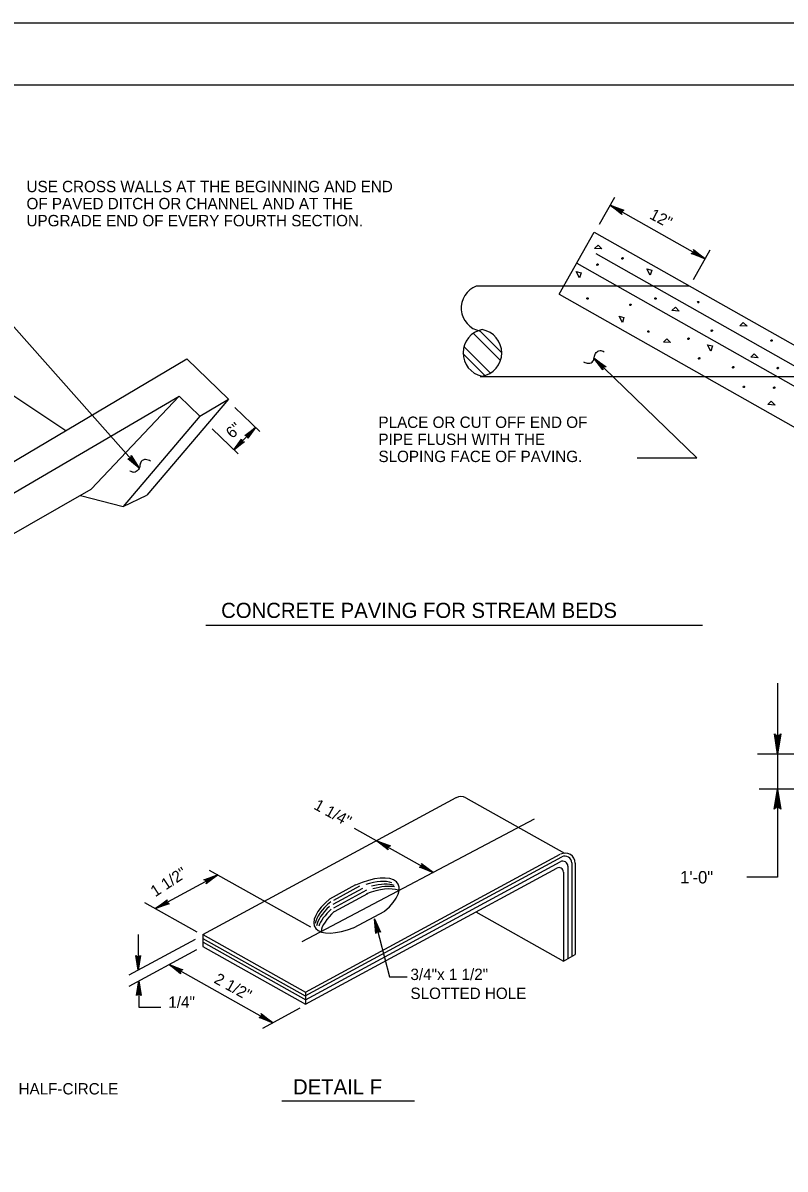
# Model space of a CAD drawing. Extents: x 5 to 910, y -47 to 547.
# Drawn here: x 180.3 to 364.1, y 270.9 to 547.5 of the extents above; entities that cross this region are included whole.
import ezdxf

# ---------------------------------------------------------------- set-up
doc = ezdxf.new("R2010")
doc.units = 0
for name, color, linetype in [('1', 7, 'Continuous'), ('2', 7, 'Continuous'), ('3', 7, 'Continuous'), ('PLT-BNDY', 7, 'Continuous')]:
    doc.layers.add(name, color=color, linetype=linetype)

msp = doc.modelspace()

# ---------------------------------------------------------------- linework, layer by layer
at = {"layer": '1'}
msp.add_line((289.63, 484), (340.95, 484), dxfattribs=at)
msp.add_lwpolyline([(830.72, -31.53), (830.72, 532.47), (44.72, 532.47), (44.72, -31.53), (830.72, -31.53), (830.72, -5.17), (630.72, -5.17), (630.72, 59.51), (830.72, 59.51), (830.72, 88.47), (630.72, 88.47), (630.72, -31.53), (709.52, -31.53), (709.52, -5.17), (709.52, -31.53), (786.52, -31.53), (786.52, -5.17), (786.52, -17.48), (830.72, -17.48)], dxfattribs=at)
for points in [[(318.98, 493.88), (319.9, 492.94), (318.16, 493.08)], [(314.89, 487.18), (314.54, 485.94), (313.74, 487.5)], [(331.91, 487.82), (331.57, 486.58), (330.77, 488.14)], [(337.63, 478.9), (338.54, 477.96), (336.81, 478.1)], [(325.23, 476.43), (324.89, 475.19), (324.09, 476.75)], [(354.01, 475.21), (354.93, 474.28), (353.19, 474.41)], [(335.57, 471.28), (336.49, 470.34), (334.75, 470.48)], [(346.55, 469.52), (346.21, 468.28), (345.41, 469.84)], [(356.66, 467.62), (357.58, 466.68), (355.84, 466.82)], [(360.76, 456.2), (361.67, 455.26), (359.94, 455.4)]]:
    msp.add_lwpolyline(points, close=True, dxfattribs=at)
for centre in [(324.86, 490.66), (318.82, 489.15), (316.46, 480.98), (326.81, 479.47), (332.82, 480.98), (343.16, 480.11), (331.11, 473.02), (346.39, 473.22), (340.78, 471.28), (360.8, 470.84), (343.37, 466.54), (351.56, 464.39), (362.31, 464.19), (354.15, 459.66), (361.47, 459.45)]:
    msp.add_ellipse(centre, major_axis=(-0.048, -0.184), ratio=0.9, dxfattribs=at)
at = {"layer": '2'}
for p, q in [((319.3, 498.92), (323.03, 505.46)), ((321.91, 503.49), (344.79, 490.57)), ((309.6, 482.01), (318.05, 496.95)), ((318.05, 496.95), (379.59, 462.15)), ((342, 485.6), (346.03, 492.74)), ((318.43, 491.8), (378.44, 457.87)), ((313.84, 489.49), (377.32, 453.59)), ((309.6, 482.01), (375.08, 444.99)), ((178.09, 474.18), (208.3, 440.06)), ((290.52, 473.13), (295.76, 467.89)), ((288.92, 472.56), (295.46, 466.04)), ((286.4, 467.69), (291.85, 462.26)), ((286.63, 469.36), (293.04, 462.95)), ((159.77, 430.8), (219.81, 466.4)), ((219.81, 466.4), (229.83, 456.67)), ((318, 466.57), (342.77, 442.57)), ((290.57, 462.15), (379.59, 462.15)), ((174.96, 459.62), (190.66, 449.12)), ((164.58, 426.13), (217.93, 457.43)), ((196.77, 434.94), (217.95, 457.45)), ((229.83, 456.67), (210.15, 433.52)), ((217.95, 457.45), (222.96, 452.6)), ((222.96, 452.6), (229.83, 456.67)), ((222.96, 452.6), (229.83, 456.67)), ((231.38, 454.68), (237.38, 448.87)), ((222.96, 452.6), (204.43, 430.8)), ((225.94, 449.56), (232.18, 443.49)), ((231.18, 444.48), (236.39, 449.83)), ((328.42, 442.57), (342.77, 442.57)), ((142.93, 404.33), (196.77, 434.94)), ((194.16, 433.45), (204.43, 430.8)), ((204.43, 430.8), (210.15, 433.52)), ((344.2, 402.04), (224.36, 402.04)), ((362.28, 388.19), (362.28, 371.06)), ((426.73, 371.06), (357.43, 371.06)), ((362.28, 371.06), (362.28, 362.6)), ((380.12, 362.6), (357.86, 362.6)), ((362.28, 362.6), (362.28, 341.37)), ((223.68, 327.49), (284.74, 360.55)), ((287.1, 360.53), (310.91, 347.16)), ((303.57, 355.33), (247.56, 325.73)), ((260.15, 353.21), (279.2, 342.5)), ((248.34, 312.73), (310.23, 346.23)), ((248.45, 313.6), (309.88, 346.87)), ((225.23, 343.05), (249.62, 329.34)), ((248.43, 311.79), (309.86, 345.06)), ((248.45, 310.74), (309.01, 343.55)), ((311.69, 343.98), (311.69, 321.68)), ((312.65, 344.79), (312.65, 322.23)), ((313.5, 344.72), (313.5, 322.68)), ((212.24, 333.76), (227.29, 341.9)), ((310.64, 342.57), (310.64, 321.11)), ((362.28, 341.37), (354.84, 341.37)), ((254.33, 336.16), (260.58, 339.55)), ((255.14, 334.83), (262.27, 338.7)), ((255.25, 333.94), (263.23, 338.29)), ((255.27, 335.84), (261.54, 339.25)), ((255.39, 333.05), (263.44, 337.42)), ((209.61, 335.22), (222.21, 328.15)), ((260.03, 329.14), (267.54, 333.19)), ((289.48, 332.96), (310.64, 321.11)), ((265.06, 331.33), (268.68, 317.33)), ((205.9, 317.77), (221.87, 326.41)), ((208.05, 327.49), (208.05, 318.93)), ((223.65, 326.57), (248.34, 312.73)), ((223.68, 327.49), (248.45, 313.6)), ((223.68, 327.49), (223.68, 324.63)), ((205.92, 315.04), (222.19, 323.87)), ((223.68, 324.63), (248.45, 310.74)), ((223.75, 325.64), (248.52, 311.75)), ((310.64, 321.11), (313.5, 322.68)), ((215.56, 320.26), (240.54, 306.23)), ((208.23, 316.32), (208.23, 309.96)), ((268.68, 317.33), (272.93, 317.33)), ((248.45, 313.6), (248.45, 310.74)), ((208.23, 309.96), (213.56, 309.96)), ((238.14, 304.95), (247.13, 309.83)), ((274.72, 287.31), (242.75, 287.31))]:
    msp.add_line(p, q, dxfattribs=at)
for centre, radius, start, end in [((291.66, 478.69), 5.68, 111.014, 258.5133), ((292.15, 467.86), 5.73, 101.3755, 257.9127), ((290.08, 467.87), 5.68, 278.8417, 80.4465), ((285.9, 358.39), 2.44, 60.7347, 118.4286), ((311.05, 344.72), 2.44, 0, 118.4349), ((311, 344.78), 1.65, 0, 118.4241), ((309.54, 342.57), 1.1, 0, 118.4375), ((310.46, 343.98), 1.24, 0, 118.4388)]:
    msp.add_arc(centre, radius, start, end, dxfattribs=at)
for centre, start_param, end_param in [((260.85, 334.36), 2.061561, 4.528802), ((260.76, 333.54), 3.509765, 4.274889), ((262.36, 331.73), 3.509765, 4.413542), ((261.34, 332.88), 3.509765, 4.189593), ((262.14, 332.37), 3.627721, 4.236382), ((260.63, 334.64), 5.155673, 7.585653), ((260.95, 334.04), 5.174005, 5.990096), ((261.29, 333.47), 5.255034, 5.990096), ((261.68, 332.74), 5.250975, 5.872331), ((262.34, 332.12), 5.242115, 5.990096)]:
    msp.add_ellipse(centre, major_axis=(-9.95, -5.32), ratio=0.421892, start_param=start_param, end_param=end_param, dxfattribs=at)
at = {"layer": '3'}
for points in [[(324.61, 501.5), (324.61, 501.75), (321.91, 503.49), (324.61, 501.5), (324.68, 501.27), (321.91, 503.49), (324.77, 502.05), (325, 502.21), (321.91, 503.49), (325.23, 502.26), (325, 502.21)], [(342.09, 492.56), (342.09, 492.3), (344.79, 490.57), (342.09, 492.56), (342.02, 492.78), (344.79, 490.57), (341.93, 492.01), (341.7, 491.85), (344.79, 490.57), (341.47, 491.8), (341.7, 491.85)], [(320.1, 463.96), (320.17, 464.21), (318, 466.57), (320.1, 463.96), (320.13, 463.73), (318, 466.57), (320.4, 464.46), (320.65, 464.55), (318, 466.57), (320.9, 464.53), (320.65, 464.55)], [(234.04, 447.96), (234.27, 447.89), (236.39, 449.83), (234.04, 447.96), (233.83, 447.93), (236.39, 449.83), (234.47, 447.68), (234.56, 447.45), (236.39, 449.83), (234.56, 447.25), (234.56, 447.45)], [(233.51, 446.35), (233.28, 446.42), (231.18, 444.48), (233.51, 446.35), (233.72, 446.38), (231.18, 444.48), (233.08, 446.63), (233.01, 446.86), (231.18, 444.48), (233.01, 447.06), (233.01, 446.86)], [(206.4, 442.83), (206.31, 442.58), (208.3, 440.06), (206.4, 442.83), (206.4, 443.06), (208.3, 440.06), (206.06, 442.35), (205.8, 442.28), (208.3, 440.06), (205.58, 442.3), (205.8, 442.28)], [(362.86, 375.68), (362.52, 375.51), (362.28, 371.06), (362.86, 375.68), (363.06, 375.91), (362.28, 371.06), (362.06, 375.5), (361.73, 375.66), (362.28, 371.06), (361.51, 375.91), (361.73, 375.66)], [(361.7, 357.99), (362.03, 358.16), (362.28, 362.6), (361.7, 357.99), (361.49, 357.75), (362.28, 362.6), (362.5, 358.16), (362.83, 358), (362.28, 362.6), (363.05, 357.75), (362.83, 358)], [(268.31, 348.15), (268.31, 348.42), (265.61, 350.14), (268.31, 348.15), (268.38, 347.94), (265.61, 350.14), (268.47, 348.72), (268.7, 348.86), (265.61, 350.14), (268.93, 348.9), (268.7, 348.86)], [(276.5, 344.49), (276.5, 344.21), (279.2, 342.5), (276.5, 344.49), (276.43, 344.69), (279.2, 342.5), (276.34, 343.92), (276.11, 343.78), (279.2, 342.5), (275.89, 343.73), (276.11, 343.78)], [(224.18, 340.69), (224.39, 340.53), (227.29, 341.9), (224.18, 340.69), (223.95, 340.74), (227.29, 341.9), (224.55, 340.23), (224.57, 339.98), (227.29, 341.9), (224.48, 339.75), (224.57, 339.98)], [(215.35, 334.97), (215.14, 335.13), (212.24, 333.76), (215.35, 334.97), (215.58, 334.92), (212.24, 333.76), (214.98, 335.43), (214.96, 335.68), (212.24, 333.76), (215.05, 335.91), (214.96, 335.68)], [(265.5, 327.99), (265.7, 328.18), (265.06, 331.31), (265.5, 327.99), (265.38, 327.79), (265.06, 331.31), (266.03, 328.24), (266.28, 328.2), (265.06, 331.31), (266.48, 328.06), (266.28, 328.2)], [(208.46, 322.25), (208.23, 322.14), (208.05, 318.93), (208.46, 322.25), (208.62, 322.43), (208.05, 318.93), (207.89, 322.14), (207.66, 322.25), (208.05, 318.93), (207.5, 322.43), (207.66, 322.25)], [(218.25, 318.27), (218.25, 318.54), (215.56, 320.26), (218.25, 318.27), (218.32, 318.06), (215.56, 320.26), (218.41, 318.84), (218.64, 318.98), (215.56, 320.26), (218.87, 319.02), (218.64, 318.98)], [(207.82, 313.01), (208.05, 313.12), (208.23, 316.32), (207.82, 313.01), (207.66, 312.82), (208.23, 316.32), (208.39, 313.12), (208.62, 313.01), (208.23, 316.32), (208.78, 312.82), (208.62, 313.01)], [(237.84, 308.23), (237.84, 307.95), (240.54, 306.23), (237.84, 308.23), (237.77, 308.43), (240.54, 306.23), (237.68, 307.65), (237.45, 307.52), (240.54, 306.23), (237.22, 307.47), (237.45, 307.52)]]:
    msp.add_lwpolyline(points, dxfattribs=at)
for points in [[(315.51, 465.72), (316.08, 465.44), (317.29, 465.49), (318, 466.29), (318.11, 467.05), (318.55, 467.92), (319.46, 468.4), (319.88, 468.37), (320.47, 468.1)], [(211.07, 441.75), (210.49, 442.01), (209.28, 442.01), (208.57, 441.18), (208.46, 440.41), (208.02, 439.56), (207.11, 439.03), (206.7, 439.08), (206.1, 439.35)]]:
    msp.add_spline(points, degree=3, dxfattribs=at)
at = {"layer": 'PLT-BNDY'}
msp.add_lwpolyline([(4.72, 547.47), (845.72, 547.47), (845.72, -46.53), (4.72, -46.53)], close=True, dxfattribs=at)

# ---------------------------------------------------------------- texts
at = {"layer": '2'}
for s, p in [('USE CROSS WALLS AT THE BEGINNING AND END', (181.15, 506.63)), ('OF PAVED DITCH OR CHANNEL AND AT THE', (181.15, 502.51)), ('UPGRADE END OF EVERY FOURTH SECTION.', (181.15, 498.4)), ('PLACE OR CUT OFF END OF', (266.02, 449.75)), ('PIPE FLUSH WITH THE', (266.02, 445.63)), ('SLOPING FACE OF PAVING.', (266.02, 441.51))]:
    msp.add_text(s, height=2.7454, dxfattribs=at).set_placement(p)
at = {"layer": '3'}
for s, rotation, p in [('12"', 332.2871, (331.16, 500.38)), ('6"', 42.2871, (230.76, 447.04)), ('1 1/4"', 331.2871, (250.22, 357.93)), ('1 1/2"', 33.2871, (212.19, 336.49)), ('2 1/2"', 331.2871, (226.15, 315.98))]:
    msp.add_text(s, height=2.745, rotation=rotation, dxfattribs=at).set_placement(p)
for s, height, p in [('CONCRETE PAVING FOR STREAM BEDS', 3.6603, (228.08, 403.9)), ('1\'-0"', 3, (338.76, 339.84)), ('3/4"x 1 1/2"', 2.7454, (273.74, 316.53)), ('1/4"', 2.745, (215.35, 309.83)), ('SLOTTED HOLE', 2.7454, (273.74, 311.96)), ('PIPE, HALF-CIRCLE', 2.7454, (168.81, 288.92)), ('DETAIL F', 3.66, (245.41, 288.95))]:
    msp.add_text(s, height=height, dxfattribs=at).set_placement(p)

doc.saveas('drawing.dxf')
